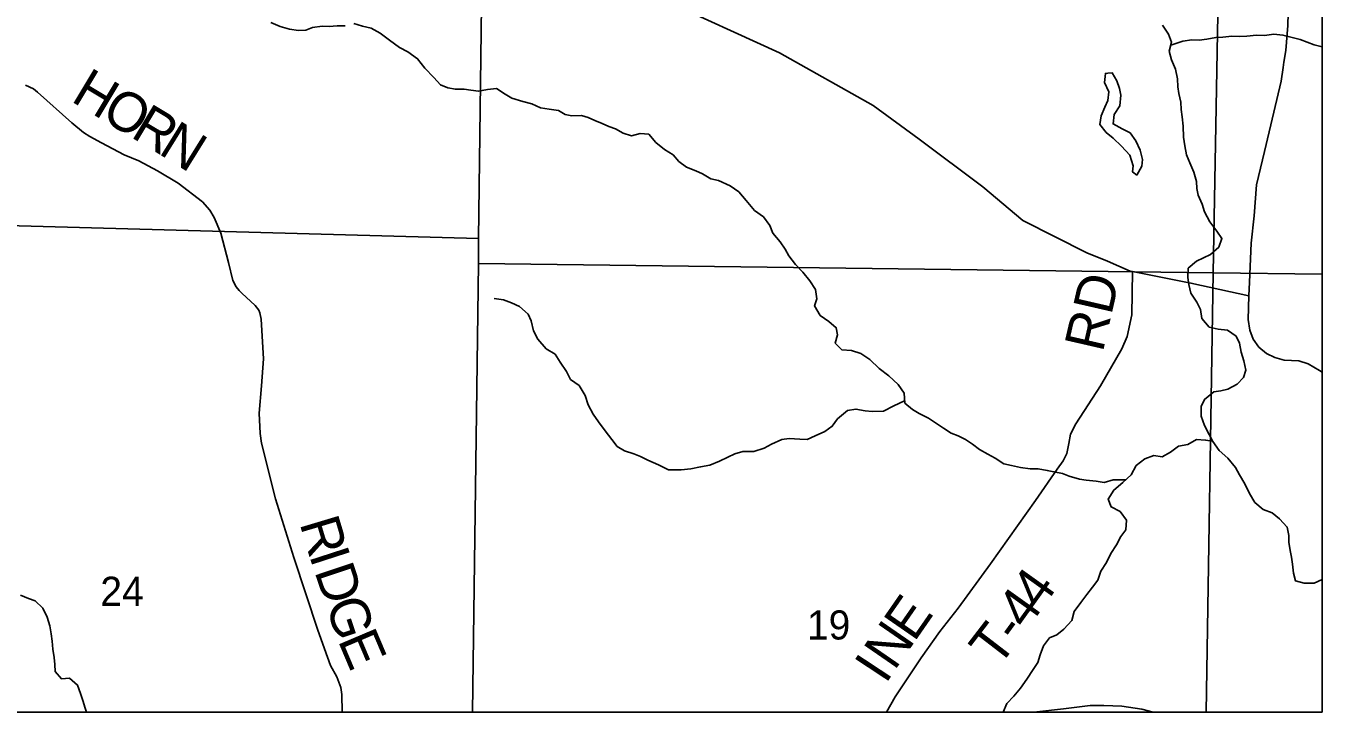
# Model space of a CAD drawing. Extents: x -452339 to 6403467, y -1 to 1814750.
# Drawn here: x -63350 to -53520, y 1547986 to 1553189 of the extents above; entities that cross this region are included whole.
import ezdxf

# ---------------------------------------------------------------- set-up
doc = ezdxf.new("R2010")
doc.units = 0
for name, color, linetype in [('GM_X_County_Road', 7, 'Continuous'), ('GM_X_County_ROW', 7, 'Continuous'), ('GM_X_Major_Lake', 7, 'Continuous'), ('GM_X_Major_Lake_Text', 7, 'Continuous'), ('GM_X_Major_River_Text', 7, 'Continuous'), ('GM_X_Section', 7, 'Continuous'), ('GM_X_Township_Road_Text', 7, 'Continuous'), ('GM_X_Unincorporated_Location', 7, 'Continuous')]:
    doc.layers.add(name, color=color, linetype=linetype)

msp = doc.modelspace()

# ---------------------------------------------------------------- linework, layer by layer
at = {"layer": 'GM_X_County_Road'}
for points in [[(-54074.7, 1551143.3), (-54513.9, 1551239.4), (-54956.8, 1551325.5), (-54974.4, 1551328.9), (-55147.6, 1551404.8), (-55304.2, 1551468.2), (-55789.9, 1551712.4), (-56093.5, 1551969.6), (-56575.7, 1552330.2), (-56923.3, 1552585.2), (-57634, 1552984.7), (-58523.1, 1553391.5), (-59488.6, 1553858), (-60265.3, 1554215.2), (-61046.1, 1554582.4), (-61573.9, 1554828.5), (-61796.9, 1554979.8), (-62272.9, 1555288.4), (-62548.2, 1555497.6), (-62897.5, 1555742.9), (-62919.8, 1555758.6), (-63040.4, 1555856.3), (-63191, 1555935.7), (-63379.6, 1556027.1)], [(-53814.9, 1552873.6), (-53808.7, 1552914.8), (-53795.4, 1553003.5), (-53780.1, 1553192.1), (-53776.5, 1553284.4), (-53798.2, 1553437.9), (-53801.2, 1553458.7), (-53856, 1553632.9), (-53974.7, 1553778.7), (-54135.5, 1553906.3), (-54160.1, 1553915.2)], [(-54070.5, 1551246.5), (-54058.2, 1551540.4), (-54035, 1551749.1), (-54015.9, 1551983.8), (-53956.7, 1552236.7), (-53885.8, 1552535.9), (-53830.6, 1552768.7), (-53814.9, 1552873.6)], [(-54074.7, 1551143.3), (-54074.7, 1551143.3), (-54070.5, 1551246.5)], [(-53519.8, 1550564.2), (-53538.7, 1550576.5), (-53626.1, 1550626.9), (-53695.7, 1550650.2), (-53808.4, 1550653.4), (-53879, 1550673.4), (-53941, 1550705.1), (-53999.6, 1550753.6), (-54041.6, 1550813), (-54067.1, 1550882.2), (-54080, 1550962.8), (-54074.7, 1551143.3)]]:
    msp.add_lwpolyline(points, dxfattribs=at)
at = {"layer": 'GM_X_County_ROW'}
for points in [[(-60952.4, 1547985.7), (-60953.3, 1548119.1), (-60961.7, 1548173.1), (-60992.2, 1548252.9), (-61038.8, 1548338.7), (-61063.3, 1548402.6), (-61136.7, 1548606.3), (-61318.5, 1549157.6), (-61457.6, 1549603.2), (-61564.5, 1550024.9), (-61573, 1550097), (-61580.1, 1550251.1), (-61563.6, 1550459.6), (-61547, 1550664), (-61565.2, 1550966.3), (-61575.5, 1551014.3), (-61583.6, 1551034.3), (-61611.9, 1551068.1), (-61712.5, 1551163.4), (-61732.6, 1551181.3), (-61754.8, 1551209.2), (-61781.1, 1551259), (-61814.1, 1551395), (-61871.6, 1551616.9), (-61922.5, 1551736.7), (-61954.8, 1551792.5), (-62011.2, 1551854.1), (-62194.2, 1551996.9), (-62352.8, 1552089.8), (-62493.2, 1552164.8), (-62605.5, 1552212), (-62776.1, 1552302.8), (-62866.4, 1552350.2), (-62914.6, 1552379.8), (-63003, 1552453.2), (-63262.6, 1552685.6), (-63292.7, 1552711.4), (-63352.9, 1552738.9)], [(-56823.9, 1547985.7), (-56758.5, 1548101.7), (-56560.9, 1548396.4), (-56419.1, 1548596.9), (-56279.2, 1548773.3), (-56035.6, 1549110.2), (-55694.1, 1549591.3), (-55528.4, 1549827.9), (-55484.4, 1549890), (-55454.5, 1549946.2), (-55440.6, 1550022.3), (-55426.6, 1550092.4), (-55386.7, 1550172.6), (-55201, 1550459.2), (-55039.3, 1550739.8), (-54997.4, 1550834), (-54961.5, 1550998.3), (-54956.8, 1551325.5)]]:
    msp.add_lwpolyline(points, dxfattribs=at)
at = {"layer": 'GM_X_Major_River_Text'}
for points in [[(-55143.8, 1552830.2), (-55163.4, 1552828.6), (-55169.2, 1552760.6), (-55137, 1552688.6), (-55144.8, 1552622.5), (-55166.7, 1552572.4), (-55196.4, 1552508.2), (-55206.2, 1552442.1), (-55156.1, 1552380.2), (-55104, 1552338.3), (-55041.8, 1552276.5), (-54977.6, 1552208.6), (-54951.4, 1552128.6), (-54957, 1552081.8), (-54925.2, 1552056.7)], [(-54925.2, 1552056.7), (-54887.4, 1552124.9), (-54881.5, 1552176.9), (-54899.8, 1552247), (-54932, 1552316.9), (-54976.1, 1552378.8), (-55036.2, 1552408.6), (-55104.3, 1552446.4), (-55096.5, 1552516.5), (-55052.7, 1552582.8), (-55047, 1552662.9), (-55057.1, 1552714.9), (-55075.3, 1552772.9), (-55111.5, 1552832.8), (-55143.8, 1552830.2)]]:
    msp.add_lwpolyline(points, dxfattribs=at)
at = {"layer": 'GM_X_Section'}
msp.add_lwpolyline([(-55706.4, 1547985.7), (-55480.9, 1548009.6), (-55278.9, 1548036), (-55175, 1548036.1), (-55039, 1548030.3), (-54887, 1548008.5), (-54801.1, 1547985.7)], dxfattribs=at)
at = {"layer": 'GM_X_Township_Road_Text'}
for points in [[(-60928.3, 1553190.7), (-60988.3, 1553188.5), (-61050.2, 1553184.3), (-61102.2, 1553186.1), (-61176.2, 1553175.8), (-61228.1, 1553157.6), (-61284, 1553155.4), (-61350, 1553163.2), (-61422.1, 1553185), (-61492.1, 1553214.8)], [(-60732.3, 1553171.4), (-60796.3, 1553187.2), (-60862.4, 1553207)], [(-54442.3, 1551039.3), (-54468.4, 1551095.3), (-54514.6, 1551163.2), (-54530.8, 1551227.2), (-54537, 1551281.2), (-54535.2, 1551351.3), (-54471.4, 1551405.6), (-54419.4, 1551429.8), (-54365.5, 1551456), (-54303.7, 1551512.3), (-54279.9, 1551576.4), (-54318.1, 1551632.3), (-54372.3, 1551702.2), (-54412.5, 1551778.2), (-54428.7, 1551838.2), (-54458.9, 1551906.1), (-54469, 1551956.2), (-54473.2, 1552010.2), (-54493.4, 1552080.2), (-54523.6, 1552150.2), (-54547.8, 1552212.1), (-54560, 1552280.2), (-54570.2, 1552346.2), (-54572.4, 1552428.3), (-54580.6, 1552498.3), (-54588.8, 1552554.4), (-54591, 1552610.4), (-54605.2, 1552676.4), (-54613.3, 1552726.5), (-54617.5, 1552788.5), (-54631.7, 1552860.5), (-54661.9, 1552932.5), (-54680.1, 1552996.5), (-54662.3, 1553064.6), (-54684.5, 1553126.6), (-54730.7, 1553194.6)], [(-55010.4, 1549745.8), (-55104.1, 1549747.8), (-55172, 1549725.5), (-55234, 1549737.3), (-55308, 1549745.1), (-55360, 1549752.9), (-55438.1, 1549774.6), (-55488.1, 1549794.5), (-55554.1, 1549808.3), (-55604.1, 1549818.1), (-55674.2, 1549829.9), (-55734.1, 1549829.7), (-55806.1, 1549839.4), (-55874.2, 1549855.2), (-55932.2, 1549869), (-56000.3, 1549910.8), (-56054.4, 1549942.6), (-56118.4, 1549976.4), (-56170.5, 1550016.3), (-56224.6, 1550052.1), (-56280.7, 1550080), (-56332.7, 1550099.8), (-56390.8, 1550139.6), (-56452.9, 1550179.4), (-56505, 1550213.3), (-56575.1, 1550249.1), (-56625.2, 1550278.9), (-56685.3, 1550328.8), (-56689.5, 1550402.8), (-56733.7, 1550468.7), (-56805.9, 1550536.5), (-56878, 1550590.3), (-56950.2, 1550660.2), (-57018.3, 1550706), (-57088.3, 1550727.7), (-57162.3, 1550733.5), (-57212.5, 1550783.4), (-57194.7, 1550847.5), (-57204.8, 1550899.5), (-57260.9, 1550947.3), (-57325.1, 1550993.2), (-57369.3, 1551067.1), (-57351.4, 1551119.2), (-57361.6, 1551189.2), (-57405.8, 1551255.1), (-57458, 1551321), (-57514.2, 1551380.9), (-57564.3, 1551444.8), (-57592.5, 1551496.7), (-57628.6, 1551552.7), (-57684.8, 1551618.5), (-57707, 1551676.5), (-57757.2, 1551742.4), (-57825.3, 1551790.2), (-57887.5, 1551866.1), (-57943.7, 1551931.9), (-58009.8, 1551975.7), (-58097.9, 1552017.5), (-58155.9, 1552029.3), (-58220, 1552067.1), (-58270, 1552088.9), (-58340.1, 1552118.7), (-58398.2, 1552160.6), (-58442.3, 1552212.5), (-58506.4, 1552252.3), (-58572.5, 1552304.1), (-58626.7, 1552368), (-58692.7, 1552373.7), (-58756.6, 1552355.5), (-58820.7, 1552375.3), (-58878.7, 1552409.1), (-58928.8, 1552425), (-58980.8, 1552448.8), (-59034.9, 1552470.6), (-59086.9, 1552494.5), (-59137, 1552510.3), (-59210.9, 1552508.1), (-59260.9, 1552517.9), (-59311, 1552547.7), (-59381, 1552557.5), (-59447, 1552567.3), (-59513.1, 1552597.1), (-59581.1, 1552616.9), (-59665.1, 1552640.6), (-59715.2, 1552670.5), (-59781.3, 1552714.3), (-59849.3, 1552708), (-59917.2, 1552693.8), (-59975.2, 1552701.6), (-60025.2, 1552709.4), (-60093.2, 1552709.2), (-60149.2, 1552719), (-60205.2, 1552742.8), (-60257.4, 1552796.7), (-60323.6, 1552868.5), (-60379.8, 1552940.4), (-60453.9, 1552992.2), (-60518, 1553026), (-60592.1, 1553081.8), (-60664.2, 1553133.6), (-60732.3, 1553171.4)], [(-54668.1, 1553042.4), (-54576.4, 1553073), (-54508.5, 1553083.2), (-54452.5, 1553081.4), (-54394.5, 1553089.6), (-54326.6, 1553099.9), (-54272.6, 1553104), (-54204.7, 1553112.3), (-54146.7, 1553108.5), (-54090.7, 1553110.7), (-54016.7, 1553119), (-53956.8, 1553115.2), (-53886.8, 1553125.4), (-53816.8, 1553119.6), (-53746.8, 1553101.9), (-53686.8, 1553086.1), (-53632.7, 1553066.2), (-53580.7, 1553044.4), (-53519.8, 1553031.3)], [(-56686.2, 1550345.6), (-56767.2, 1550308.5), (-56847, 1550268.2), (-56933, 1550263.8), (-56985, 1550269.7), (-57055, 1550283.4), (-57119, 1550273.2), (-57194.7, 1550208.9), (-57234.6, 1550152.7), (-57290.4, 1550114.4), (-57364.3, 1550080.1), (-57424.2, 1550053.9), (-57480.2, 1550055.7), (-57560.2, 1550059.4), (-57618.1, 1550053.2), (-57696, 1550016.9), (-57751.9, 1549986.7), (-57829.8, 1549962.4), (-57913.7, 1549962.1), (-57973.6, 1549943.9), (-58025.6, 1549919.7), (-58089.4, 1549889.4), (-58163.3, 1549859.1), (-58233.3, 1549844.9), (-58307.2, 1549830.6), (-58381.1, 1549822.3), (-58477.1, 1549822), (-58553.2, 1549859.7), (-58633.2, 1549895.5), (-58689.3, 1549923.3), (-58739.4, 1549943.2), (-58809.4, 1549966.9), (-58865.5, 1549998.8), (-58905.6, 1550052.7), (-58955.8, 1550118.6), (-59008, 1550186.5), (-59048.1, 1550244.4), (-59086.3, 1550314.3), (-59108.5, 1550386.3), (-59154.8, 1550462.2), (-59218.9, 1550508), (-59251, 1550568), (-59297.2, 1550639.9), (-59337.4, 1550699.8), (-59403.5, 1550739.6), (-59467.7, 1550813.4), (-59499.9, 1550877.4), (-59518.1, 1550951.4), (-59540.2, 1551003.3), (-59606.4, 1551061.2), (-59666.4, 1551089), (-59728.5, 1551110.8), (-59798.5, 1551122.6)], [(-53519.8, 1548990.6), (-53580.3, 1548964.4), (-53656.2, 1548962.1), (-53722.3, 1548981.9), (-53736.4, 1549037.9), (-53744.7, 1549108), (-53750.8, 1549160), (-53763, 1549212), (-53771.1, 1549274), (-53771.3, 1549324), (-53783.5, 1549388.1), (-53841.6, 1549449.9), (-53897.8, 1549495.8), (-53967.8, 1549521.5), (-54030, 1549575.4), (-54070.2, 1549643.3), (-54104.4, 1549717.2), (-54146.6, 1549785.2), (-54176.7, 1549841.1), (-54234.9, 1549911), (-54299.1, 1549968.8), (-54349.2, 1550036.7), (-54375.4, 1550090.7), (-54411.6, 1550158.6), (-54435.8, 1550228.6), (-54436, 1550302.6), (-54412.2, 1550356.8), (-54340.4, 1550413.1), (-54288.4, 1550421.3), (-54234.5, 1550435.5), (-54162.6, 1550471.8), (-54116.8, 1550524), (-54097, 1550578.1), (-54113.2, 1550650.1), (-54133.4, 1550714.1), (-54145.6, 1550784.1), (-54171.7, 1550836.1), (-54237.8, 1550881.9), (-54307.9, 1550889.7), (-54375.9, 1550903.4), (-54432.1, 1550971.3), (-54442.3, 1551039.3)], [(-54350.7, 1550039.7), (-54403.3, 1550048.5), (-54473.2, 1550052.3), (-54539.1, 1550014), (-54609.1, 1550001.8), (-54668.9, 1549955.5), (-54732.8, 1549921.2), (-54794.8, 1549931), (-54864.7, 1549906.8), (-54930.5, 1549854.5), (-54968.3, 1549784.3), (-55032.1, 1549726), (-55097.9, 1549669.7), (-55141.6, 1549599.5), (-55119.5, 1549541.5), (-55051.4, 1549505.7), (-55003.2, 1549439.9), (-55009, 1549367.8), (-55046.8, 1549317.6), (-55078.6, 1549253.4), (-55122.4, 1549187.2), (-55154.2, 1549119), (-55198, 1549054.8), (-55219.8, 1548984.7), (-55261.6, 1548932.5), (-55303.4, 1548878.3), (-55349.2, 1548816.1), (-55399, 1548747.8), (-55416.8, 1548679.7), (-55478.6, 1548613.5), (-55532.4, 1548571.2), (-55586.3, 1548549), (-55632.1, 1548486.8), (-55657.9, 1548420.7), (-55675.7, 1548362.5), (-55711.6, 1548308.4), (-55759.3, 1548234.1), (-55807.1, 1548165.9), (-55856.9, 1548105.7), (-55910.7, 1548051.4), (-55938.6, 1547985.7)], [(-62891, 1547985.7), (-62901.9, 1548014.9), (-62918.1, 1548072.9), (-62936.2, 1548126.8), (-62958.4, 1548190.8), (-63018.5, 1548242.7), (-63080.5, 1548238.4), (-63128.7, 1548294.3), (-63130.8, 1548346.4), (-63137, 1548398.4), (-63145.2, 1548462.4), (-63151.3, 1548522.4), (-63157.5, 1548578.5), (-63167.7, 1548638.5), (-63187.9, 1548706.5), (-63222.1, 1548774.4), (-63280.2, 1548830.2), (-63330.2, 1548846.1), (-63392.3, 1548871.9)]]:
    msp.add_lwpolyline(points, dxfattribs=at)
at = {"layer": 'GM_X_Unincorporated_Location'}
for points in [[(-65186.4, 1557097.3), (-59844.9, 1556964.8), (-59852, 1556682.6), (-59917, 1551575.9), (-65238.6, 1551724.6)], [(-59852, 1556682.6), (-54249.2, 1556628.8), (-54346.1, 1551317.7), (-59917, 1551387.8), (-59917, 1551575.9)], [(-53519.8, 1551307.2), (-53519.8, 1556617.7), (-54249.2, 1556628.8), (-54346.1, 1551317.7)], [(-65292.1, 1547985.7), (-59963.7, 1547985.7), (-59917, 1551387.8), (-59917, 1551575.9), (-65238.6, 1551724.6)], [(-59963.7, 1547985.7), (-54397.6, 1547985.7), (-54346.1, 1551317.7), (-59917, 1551387.8)], [(-54397.6, 1547985.7), (-53519.8, 1547985.7), (-53519.8, 1551307.2), (-54346.1, 1551317.7)]]:
    msp.add_lwpolyline(points, close=True, dxfattribs=at)

# ---------------------------------------------------------------- texts
at = {"layer": 'GM_X_Major_Lake'}
for s, p in [('24', (-62785.5, 1548791.2)), ('19', (-57426.3, 1548536))]:
    msp.add_text(s, height=220.83, rotation=0.00001, dxfattribs=at).set_placement(p)
at = {"layer": 'GM_X_Major_Lake_Text'}
for s, rotation, p in [('H', 329.04187, (-63016.7, 1552622.6)), ('O', 329.04322, (-62790.2, 1552486.8)), ('R', 329.03558, (-62563.9, 1552351)), ('N', 328.12784, (-62353.7, 1552224.8)), ('RD', 77.04182, (-55183.7, 1550706.8)), ('R', 286.67719, (-61276.3, 1549418.5)), ('I', 287.95768, (-61203.4, 1549175.5)), ('D', 288.55867, (-61164.3, 1549055)), ('4', 54.50696, (-55652, 1548752.7)), ('G', 288.65596, (-61080.1, 1548804.2)), ('E', 55.25795, (-56613.4, 1548510.8)), ('4', 54.37937, (-55760.1, 1548601.9)), ('N', 55.39354, (-56763.3, 1548293.7)), ('T', 52.44525, (-55976, 1548315.5)), ('-', 53.92265, (-55834.2, 1548500.2)), ('E', 292.99246, (-60986.9, 1548530.9)), ('I', 56.58704, (-56830.2, 1548192.2))]:
    msp.add_text(s, height=300, rotation=rotation, dxfattribs=at).set_placement(p)

doc.saveas('drawing.dxf')
